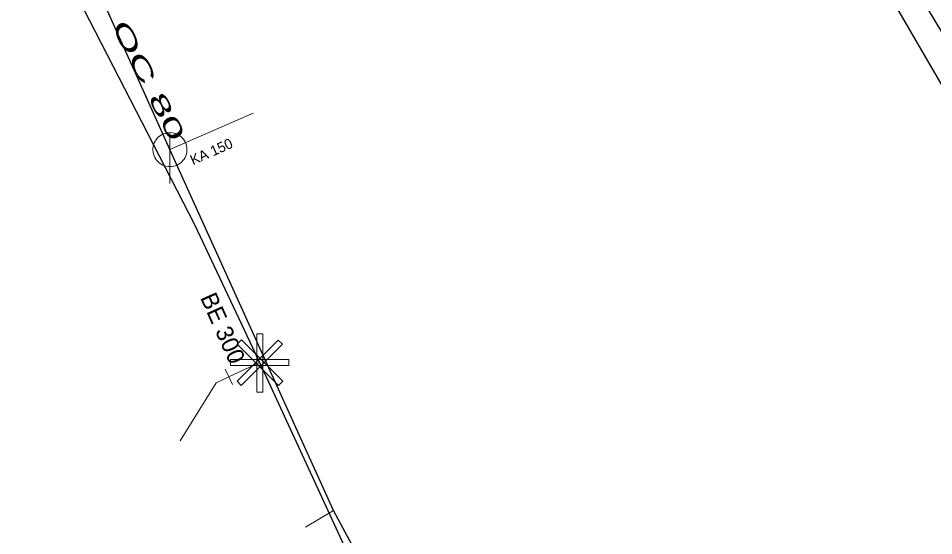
# Model space of a CAD drawing. Extents: x -809028 to -807737, y -990545 to -989489.
# Drawn here: x -808606.1 to -808552.3, y -990038.3 to -990007.9 of the extents above; entities that cross this region are included whole.
import ezdxf

# ---------------------------------------------------------------- set-up
doc = ezdxf.new("R2010")
doc.units = 0
doc.header["$LTSCALE"] = 0.32
for name, color, linetype, lineweight in [('1', 7, 'Continuous', 13), ('11', 7, 'Continuous', 13), ('12', 7, 'Continuous', 13), ('13', 7, 'Continuous', 13), ('14', 7, 'Continuous', 25), ('17', 7, 'Continuous', 25), ('22', 7, 'Continuous', 13), ('34', 7, 'Continuous', 13)]:
    doc.layers.add(name, color=color, linetype=linetype, lineweight=lineweight)

msp = doc.modelspace()

# ---------------------------------------------------------------- linework, layer by layer
at = {"layer": '11'}
for p, q in [((-808592.291, -990013.447), (-808597.186, -990015.591)), ((-808589.223, -990037.796), (-808587.566, -990036.813))]:
    msp.add_line(p, q, dxfattribs=at)
at = {"layer": '12'}
for points in [[(-808592.079, -990026.425), (-808591.728, -990026.425), (-808591.728, -990029.86), (-808592.079, -990029.86)], [(-808590.813, -990026.789), (-808590.565, -990027.037), (-808592.994, -990029.466), (-808593.24, -990029.218)], [(-808593.232, -990027.028), (-808592.985, -990026.78), (-808590.556, -990029.209), (-808590.803, -990029.457)], [(-808590.195, -990027.934), (-808590.195, -990028.284), (-808593.63, -990028.284), (-808593.63, -990027.934)]]:
    msp.add_lwpolyline(points, close=True, dxfattribs=at)
at = {"layer": '13'}
msp.add_line((-808591.921, -990028.11), (-808593.726, -990028.951), dxfattribs=at)
msp.add_lwpolyline([(-808593.726, -990028.951), (-808594.46, -990029.298), (-808596.574, -990032.715)], dxfattribs=at)
at = {"layer": '14'}
msp.add_line((-808597.186, -990015.591), (-808606.098, -989995.697), dxfattribs=at)
for points in [[(-808569.23, -989979.334), (-808568.292, -989981.1), (-808559.407, -989995.771), (-808556.033, -990001.675), (-808538.055, -990031.421), (-808535.03, -990036.115), (-808522.248, -990056.603), (-808501.469, -990070.893)], [(-808583.364, -990044.645), (-808587.566, -990036.813), (-808597.186, -990015.591)]]:
    msp.add_lwpolyline(points, dxfattribs=at)
at = {"layer": '17'}
for points in [[(-808567.463, -989984.912), (-808564.903, -989989.315), (-808559.226, -989999.059), (-808546.874, -990020.305), (-808545.364, -990022.763), (-808542.872, -990026.881), (-808542.522, -990027.583), (-808541.645, -990028.908), (-808532.624, -990043.916), (-808522.756, -990058.613), (-808516.815, -990065.144), (-808508.914, -990069.898)], [(-808605.01, -990001.965), (-808595.743, -990019.989), (-808592.335, -990027.23), (-808591.921, -990028.11), (-808591.508, -990029.003), (-808585.563, -990041.877), (-808578.065, -990058.263), (-808574.107, -990066.738), (-808572.19, -990070.92), (-808570.028, -990075.541), (-808569.819, -990075.989)]]:
    msp.add_lwpolyline(points, dxfattribs=at)
at = {"layer": '22'}
msp.add_line((-808597.186, -990017.591), (-808597.185, -990014.591), dxfattribs=at)
msp.add_lwpolyline([(-808596.186, -990015.591), (-808596.191, -990015.482), (-808596.209, -990015.374), (-808596.239, -990015.268), (-808596.279, -990015.167), (-808596.331, -990015.07), (-808596.393, -990014.98), (-808596.465, -990014.897), (-808596.545, -990014.823), (-808596.633, -990014.757), (-808596.727, -990014.702), (-808596.827, -990014.657), (-808596.932, -990014.624), (-808597.039, -990014.602), (-808597.148, -990014.592), (-808597.258, -990014.594), (-808597.366, -990014.608), (-808597.473, -990014.633), (-808597.576, -990014.67), (-808597.674, -990014.719), (-808597.766, -990014.777), (-808597.852, -990014.846), (-808597.929, -990014.923), (-808597.998, -990015.009), (-808598.057, -990015.101), (-808598.105, -990015.199), (-808598.142, -990015.302), (-808598.168, -990015.409), (-808598.182, -990015.517), (-808598.185, -990015.627), (-808598.175, -990015.736), (-808598.154, -990015.843), (-808598.12, -990015.947), (-808598.076, -990016.047), (-808598.021, -990016.142), (-808597.955, -990016.23), (-808597.881, -990016.31), (-808597.798, -990016.382), (-808597.708, -990016.444), (-808597.612, -990016.496), (-808597.51, -990016.537), (-808597.405, -990016.567), (-808597.297, -990016.585), (-808597.187, -990016.591), (-808597.078, -990016.585), (-808596.97, -990016.567), (-808596.865, -990016.538), (-808596.763, -990016.497), (-808596.666, -990016.445), (-808596.576, -990016.383), (-808596.493, -990016.312), (-808596.418, -990016.232), (-808596.353, -990016.144), (-808596.297, -990016.05), (-808596.253, -990015.95), (-808596.219, -990015.846), (-808596.197, -990015.738), (-808596.187, -990015.629)], close=True, dxfattribs=at)
at = {"layer": '34'}
msp.add_line((-808593.937, -990028.497), (-808593.515, -990029.404), dxfattribs=at)

# ---------------------------------------------------------------- texts
at = {"layer": '1', "width": 2}
msp.add_text('OC 80 ', height=1, rotation=297, dxfattribs=at).set_placement((-808600.643, -990008.303))
at = {"layer": '1'}
for s, height, rotation, p in [('KA 150', 0.6, 24, (-808595.829, -990016.515)), ('BE 300', 1, 294, (-808595.422, -990024.289))]:
    msp.add_text(s, height=height, rotation=rotation, dxfattribs=at).set_placement(p)

doc.saveas('drawing.dxf')
